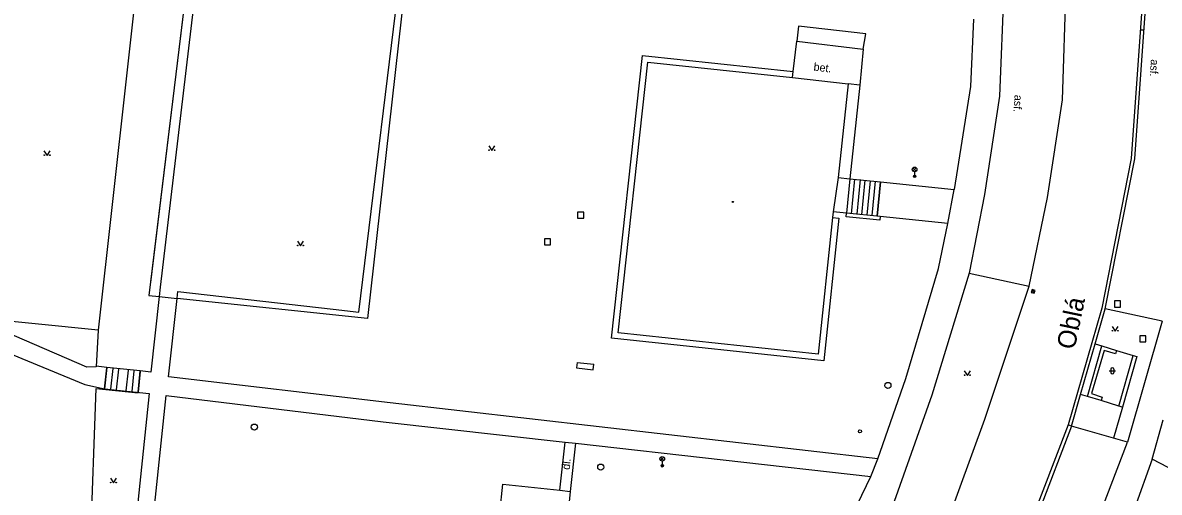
# Model space of a CAD drawing. Extents: x -602419 to -601554, y -1162937 to -1162362.
# Drawn here: x -601838.6 to -601746.3, y -1162494 to -1162455.9 of the extents above; entities that cross this region are included whole.
import ezdxf

# ---------------------------------------------------------------- set-up
doc = ezdxf.new("R2010")
doc.units = 0
doc.layers.add('Podklad', color=7, linetype='Continuous')

msp = doc.modelspace()

# ---------------------------------------------------------------- linework, layer by layer
at = {"layer": 'Podklad'}
for p, q in [((-601766.3225, -1162467.93), (-601766.0575, -1162467.665)), ((-601766.3225, -1162467.665), (-601766.0575, -1162467.93)), ((-601766.19, -1162467.985), (-601766.19, -1162468.36)), ((-601756.5999, -1162477.8185), (-601756.5201, -1162477.5815)), ((-601750.383, -1162484.148), (-601749.883, -1162484.148)), ((-601750.258, -1162484.023), (-601750.258, -1162484.273)), ((-601750.008, -1162484.023), (-601750.008, -1162484.273)), ((-601786.8125, -1162491.43), (-601786.5475, -1162491.165)), ((-601786.8125, -1162491.165), (-601786.5475, -1162491.43)), ((-601786.68, -1162491.485), (-601786.68, -1162491.86))]:
    msp.add_line(p, q, dxfattribs=at)
for points in [[(-601759.7, -1162404.55), (-601753.15, -1162419.52), (-601749.88, -1162432.78), (-601748.51, -1162442.04), (-601747.59, -1162452.46), (-601748.62, -1162466.9), (-601751, -1162479.06), (-601751.81, -1162481.88), (-601753.73, -1162488.54)], [(-601822.13, -1162447.02), (-601824.55, -1162446.72), (-601828.37, -1162478.04), (-601827.52, -1162478.12), (-601826.06, -1162478.28)], [(-601824.49, -1162446.24), (-601828.24, -1162476.98)], [(-601769.18, -1162491.29), (-601808.78, -1162486.76), (-601826.77, -1162484.63), (-601826.06, -1162478.28), (-601826.06, -1162478.24), (-601826, -1162477.71), (-601813.39, -1162479.15), (-601811.31, -1162479.39), (-601807.65, -1162449.55), (-601823.91, -1162447.44), (-601827.44, -1162477.36), (-601827.52, -1162478.12), (-601828.2, -1162484.27), (-601829.06, -1162484.16), (-601831.79, -1162483.87), (-601832.64, -1162483.78)], [(-601822.13, -1162447.02), (-601807.12, -1162448.84), (-601810.61, -1162479.89), (-601826.06, -1162478.28)], [(-601837.55, -1162448.85), (-601829.04, -1162449.96), (-601832.49, -1162480.85)], [(-601750.71, -1162479.13), (-601748.32, -1162466.94), (-601747.29, -1162452.46)], [(-601758.94, -1162453.05), (-601759.31, -1162461.84), (-601760.52, -1162469.84), (-601761.77, -1162476.23)], [(-601756.88, -1162477.28), (-601755.39, -1162470.09), (-601754.18, -1162462.14), (-601753.88, -1162452.88)], [(-601770.38, -1162458.03), (-601770.16, -1162456.7899), (-601775.62, -1162456.1799), (-601775.76, -1162457.38)], [(-601761.4099, -1162455.6), (-601761.64, -1162461.06), (-601762.9699, -1162469.44)], [(-601747.876, -1162456.47), (-601747.5751, -1162456.47)], [(-601776.05, -1162459.85), (-601775.76, -1162457.38)], [(-601775.76, -1162457.38), (-601770.38, -1162458.03)], [(-601770.38, -1162458.03), (-601770.63, -1162460.96)], [(-601772.85, -1162471.7), (-601772.35, -1162471.75), (-601773.56, -1162483.34), (-601790.81, -1162481.5), (-601788.28, -1162458.54), (-601776.05, -1162459.85)], [(-601790.26, -1162481.06), (-601787.84, -1162459.09)], [(-601787.84, -1162459.09), (-601776.11, -1162460.34)], [(-601776.11, -1162460.34), (-601776.05, -1162459.85)], [(-601776.11, -1162460.34), (-601771.58, -1162460.86)], [(-601771.58, -1162460.86), (-601772.4099, -1162468.45)], [(-601770.63, -1162460.96), (-601771.58, -1162460.86)], [(-601770.63, -1162460.96), (-601771.46, -1162468.55)], [(-601836.88, -1162466.295), (-601836.63, -1162466.67), (-601836.38, -1162466.295)], [(-601800.77, -1162465.885), (-601800.52, -1162466.26), (-601800.27, -1162465.885)], [(-601772.4099, -1162468.45), (-601772.8, -1162471.25)], [(-601772.4099, -1162468.45), (-601771.46, -1162468.55)], [(-601771.46, -1162468.55), (-601771.7199, -1162471.36)], [(-601771.46, -1162468.55), (-601768.96, -1162468.8)], [(-601771.31, -1162471.4), (-601771.04, -1162468.59)], [(-601770.62, -1162468.63), (-601770.89, -1162471.44)], [(-601770.4699, -1162471.48), (-601770.21, -1162468.68)], [(-601769.79, -1162468.7199), (-601770.06, -1162471.52)], [(-601769.64, -1162471.55), (-601769.37, -1162468.76)], [(-601769.2199, -1162471.5889), (-601768.96, -1162468.8)], [(-601768.96, -1162468.8), (-601769.2199, -1162471.59)], [(-601768.96, -1162468.8), (-601762.9699, -1162469.44)], [(-601763.49, -1162472.2), (-601762.9699, -1162469.44)], [(-601772.85, -1162471.7), (-601774.01, -1162482.79)], [(-601772.8, -1162471.25), (-601772.85, -1162471.7)], [(-601771.7199, -1162471.36), (-601772.8, -1162471.25)], [(-601768.99, -1162471.61), (-601769.02, -1162471.9099), (-601771.75, -1162471.6599), (-601771.7199, -1162471.36)], [(-601768.99, -1162471.61), (-601771.7199, -1162471.36)], [(-601763.49, -1162472.2), (-601768.99, -1162471.61)], [(-601769.18, -1162491.29), (-601766.89, -1162484.78), (-601764.25, -1162475.84), (-601763.49, -1162472.2)], [(-601816.3, -1162473.625), (-601816.05, -1162474), (-601815.8, -1162473.625)], [(-601761.77, -1162476.23), (-601764.78, -1162486.14)], [(-601761.77, -1162476.23), (-601756.88, -1162477.28)], [(-601763.6599, -1162496.77), (-601760.48, -1162488.08), (-601756.88, -1162477.28)], [(-601751.52, -1162481.96), (-601750.71, -1162479.13)], [(-601746.09, -1162480.13), (-601750.71, -1162479.13)], [(-601832.64, -1162483.82), (-601833.4, -1162483.86), (-601842.75, -1162479.83)], [(-601832.49, -1162480.85), (-601842.75, -1162479.83)], [(-601746.09, -1162480.13), (-601748.9, -1162489.95)], [(-601848, -1162480.38), (-601847.54, -1162480.87), (-601842.9, -1162481.43), (-601833.56, -1162485.27), (-601831.9699, -1162485.6), (-601828.34, -1162485.99), (-601829.67, -1162498.74), (-601831.12, -1162513.1599), (-601831.45, -1162518.38), (-601831.42, -1162528.19), (-601830.48, -1162545.34)], [(-601832.49, -1162480.85), (-601832.64, -1162483.82)], [(-601774.01, -1162482.79), (-601790.26, -1162481.06)], [(-601750.1599, -1162480.545), (-601749.9099, -1162480.92), (-601749.6599, -1162480.545)], [(-601753.44, -1162488.63), (-601752.71, -1162486.08), (-601751.52, -1162481.96)], [(-601751.52, -1162481.96), (-601751, -1162482.12)], [(-601752.1599, -1162486.23), (-601751, -1162482.12)], [(-601749.8, -1162482.49), (-601749.89, -1162482.77), (-601750.8, -1162482.49), (-601751.82, -1162486), (-601750.96, -1162486.28), (-601751.04, -1162486.57)], [(-601751, -1162482.12), (-601749.8, -1162482.49)], [(-601749.8, -1162482.49), (-601748.45, -1162482.9)], [(-601749.62, -1162487.01), (-601748.45, -1162482.9)], [(-601748.45, -1162482.9), (-601748.15, -1162482.99)], [(-601793.58, -1162483.4699), (-601793.63, -1162483.92)], [(-601793.58, -1162483.4699), (-601792.24, -1162483.61)], [(-601792.29, -1162484.06), (-601792.24, -1162483.61)], [(-601748.15, -1162482.99), (-601749.3, -1162487.11)], [(-601831.79, -1162483.87), (-601831.97, -1162485.6)], [(-601831.9699, -1162485.6), (-601831.79, -1162483.9099)], [(-601831.3, -1162483.9699), (-601831.4699, -1162485.65)], [(-601830.98, -1162485.7), (-601830.8, -1162484.02)], [(-601830.05, -1162484.1), (-601830.23, -1162485.78)], [(-601829.73, -1162485.84), (-601829.55, -1162484.15)], [(-601829.24, -1162485.89), (-601829.06, -1162484.16)], [(-601829.06, -1162484.2), (-601829.24, -1162485.89)], [(-601793.63, -1162483.92), (-601792.29, -1162484.06)], [(-601762.1599, -1162484.155), (-601761.9099, -1162484.53), (-601761.6599, -1162484.155)], [(-601833.1, -1162498.35), (-601832.63, -1162485.58), (-601829.24, -1162485.94)], [(-601828.28, -1162498.78), (-601826.96, -1162486.1599)], [(-601826.96, -1162486.1599), (-601809.34, -1162488.28)], [(-601764.78, -1162486.14), (-601767.86, -1162494.76)], [(-601752.16, -1162486.23), (-601752.71, -1162486.08)], [(-601751.04, -1162486.57), (-601752.1599, -1162486.23)], [(-601749.62, -1162487.01), (-601751.04, -1162486.57)], [(-601749.3, -1162487.11), (-601750.0515, -1162489.6152)], [(-601749.3, -1162487.11), (-601749.62, -1162487.01)], [(-601809.34, -1162488.28), (-601794.57, -1162489.93)], [(-601746.9099, -1162491.32), (-601746.01, -1162488.13)], [(-601753.73, -1162488.54), (-601758.99, -1162502.27), (-601763.57, -1162510.73), (-601765.2151, -1162512.8049), (-601770.46, -1162519.42), (-601773.43, -1162522.8), (-601777.69, -1162527.38), (-601781.11, -1162530.89), (-601783.81, -1162533.48), (-601789.65, -1162538.44), (-601795.53, -1162542.8), (-601801.99, -1162546.98), (-601807.25, -1162549.95), (-601810.9, -1162551.81), (-601819.27, -1162555.34), (-601821.43, -1162556.31)], [(-601753.44, -1162488.63), (-601758.71, -1162502.4), (-601763.35, -1162510.94), (-601764.92, -1162513.03), (-601770.02, -1162519.59), (-601773.42, -1162523.45)], [(-601753.44, -1162488.63), (-601753.73, -1162488.54)], [(-601748.9, -1162489.95), (-601753.44, -1162488.63)], [(-601795, -1162493.83), (-601794.57, -1162489.93)], [(-601794.57, -1162489.93), (-601793.7199, -1162490.03)], [(-601793.7199, -1162490.03), (-601794.1599, -1162493.96)], [(-601793.7199, -1162490.03), (-601769.74, -1162492.7199)], [(-601769.8, -1162526.28), (-601765.98, -1162521.88), (-601762.4303, -1162517.217), (-601759.38, -1162513.21), (-601754.29, -1162504.02), (-601748.9, -1162489.95)], [(-601769.74, -1162492.72), (-601769.18, -1162491.29)], [(-601746.9099, -1162491.32), (-601749.77, -1162499.32), (-601752.3, -1162505.09)], [(-601741.77, -1162493.99), (-601746.9099, -1162491.32)], [(-601831.49, -1162492.875), (-601831.24, -1162493.25), (-601830.99, -1162492.875)], [(-601790.68, -1162504.9699), (-601777.76, -1162506.38), (-601773.7199, -1162500.98), (-601769.74, -1162492.7199)], [(-601799.87, -1162495.69), (-601799.63, -1162493.34)], [(-601799.63, -1162493.34), (-601796.55, -1162493.67)], [(-601796.55, -1162493.67), (-601795, -1162493.83)], [(-601794.16, -1162493.96), (-601794.45, -1162496.96), (-601795.18, -1162504.57)], [(-601795, -1162493.83), (-601794.1599, -1162493.96)]]:
    msp.add_lwpolyline(points, dxfattribs=at)
for points in [[(-601793.55, -1162471.77), (-601793.05, -1162471.77), (-601793.05, -1162471.27), (-601793.55, -1162471.27)], [(-601796.25, -1162473.93), (-601795.75, -1162473.93), (-601795.75, -1162473.43), (-601796.25, -1162473.43)], [(-601756.4814, -1162477.8583), (-601756.4017, -1162477.6214), (-601756.6386, -1162477.5417), (-601756.7183, -1162477.7786)], [(-601749.9699, -1162478.9699), (-601749.4699, -1162478.9699), (-601749.4699, -1162478.4699), (-601749.9699, -1162478.4699)], [(-601747.9099, -1162481.81), (-601747.4099, -1162481.81), (-601747.4099, -1162481.31), (-601747.9099, -1162481.31)]]:
    msp.add_lwpolyline(points, close=True, dxfattribs=at)
for centre, radius in [((-601800.7451, -1162466.2349), 0.025), ((-601800.2954, -1162466.2349), 0.025), ((-601836.8551, -1162466.6449), 0.025), ((-601836.4054, -1162466.6449), 0.025), ((-601766.19, -1162467.7975), 0.1875), ((-601766.19, -1162468.36), 0.1), ((-601766.19, -1162468.36), 0.0723), ((-601766.19, -1162468.36), 0.0438), ((-601780.95, -1162470.44), 0.045), ((-601780.95, -1162470.44), 0.0199), ((-601816.2751, -1162473.9749), 0.025), ((-601815.8254, -1162473.9749), 0.025), ((-601750.135, -1162480.8949), 0.025), ((-601749.6853, -1162480.8949), 0.025), ((-601762.135, -1162484.5049), 0.025), ((-601761.6853, -1162484.5049), 0.025), ((-601768.36, -1162485.34), 0.25), ((-601819.8, -1162488.7199), 0.25), ((-601770.63, -1162489.07), 0.125), ((-601786.68, -1162491.2975), 0.1875), ((-601791.67, -1162491.9699), 0.25), ((-601786.68, -1162491.86), 0.1), ((-601786.68, -1162491.86), 0.0723), ((-601786.68, -1162491.86), 0.0438), ((-601831.4651, -1162493.2249), 0.025), ((-601831.0154, -1162493.2249), 0.025)]:
    msp.add_circle(centre, radius, dxfattribs=at)
for centre, start, end in [((-601750.1328, -1162484.0231), 0, 180), ((-601750.1328, -1162484.2731), 180, 0)]:
    msp.add_arc(centre, 0.125, start, end, dxfattribs=at)

# ---------------------------------------------------------------- texts
for s, height, rotation, p in [('asf.', 0.65, 265.93, (-601747, -1162458.85)), ('bet.', 0.65, 353.45, (-601774.42, -1162459.77)), ('asf.', 0.65, 265.93, (-601758.07, -1162461.73)), ('Oblá', 1.5, 78.2, (-601753.21, -1162482.49)), ('dl.', 0.65, 83.61, (-601794.2, -1162492.21))]:
    msp.add_text(s, height=height, rotation=rotation, dxfattribs=at).set_placement(p)

doc.saveas('drawing.dxf')
